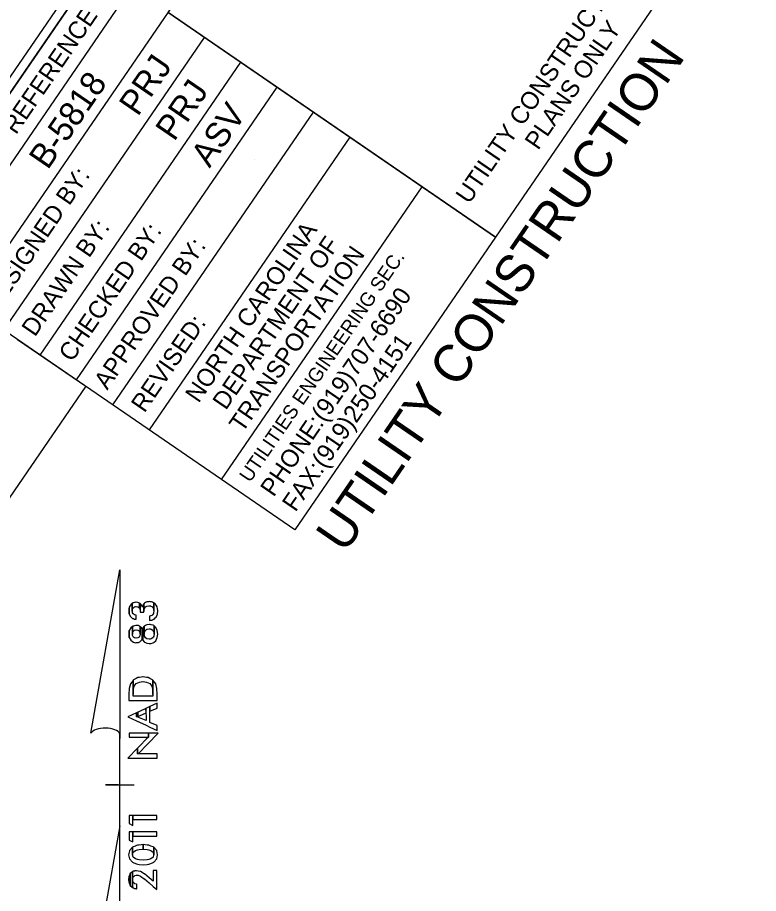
# Model space of a CAD drawing. Extents: x 1439200 to 1641919, y 393684 to 606444.
# Drawn here: x 1641528.9 to 1641613.1, y 394338.4 to 394437.9 of the extents above; entities that cross this region are included whole.
import ezdxf

# ---------------------------------------------------------------- set-up
doc = ezdxf.new("R2010")
doc.units = 0
for name, color, linetype in [('North Arrow NAD83 CELL', 7, 'Continuous'), ('Sheet Data Field CELL', 7, 'Continuous'), ('Sheet Plot Border Inside CELL', 7, 'Continuous'), ('Sheet Sticker Exception Certification CELL', 7, 'Continuous'), ('UC Plan Sheet 34 CELL', 7, 'Continuous')]:
    doc.layers.add(name, color=color, linetype=linetype)

msp = doc.modelspace()

# ---------------------------------------------------------------- linework, layer by layer
at = {"layer": 'North Arrow NAD83 CELL'}
for p, q in [((1641537.276, 394356.616), (1641540.564, 394375.155)), ((1641540.584, 394375.155), (1641540.564, 394375.155)), ((1641540.584, 394375.155), (1641540.564, 394375.155)), ((1641540.584, 394375.155), (1641540.576, 394356.035)), ((1641540.572, 394346.115), (1641540.576, 394356.595)), ((1641540.576, 394356.035), (1641540.576, 394356.575)), ((1641538.974, 394350.755), (1641538.954, 394350.755)), ((1641540.394, 394350.755), (1641538.974, 394350.755)), ((1641538.994, 394350.755), (1641542.194, 394350.754)), ((1641540.572, 394346.115), (1641537.224, 394327.216)), ((1641540.584, 394327.295), (1641540.572, 394346.115))]:
    msp.add_line(p, q, dxfattribs=at)
for points in [[(1641542.372, 394369.561), (1641542.411, 394369.557), (1641542.411, 394370.028), (1641542.372, 394370.03), (1641542.257, 394370.057), (1641542.241, 394370.061), (1641542.239, 394370.062), (1641542.103, 394370.158), (1641542.097, 394370.168), (1641542.086, 394370.186), (1641542.019, 394370.305), (1641542.005, 394370.388), (1641542.001, 394370.412), (1641541.985, 394370.502), (1641541.985, 394371.368), (1641541.812, 394371.25), (1641541.764, 394371.168), (1641541.764, 394371.167), (1641541.625, 394370.927), (1641541.612, 394370.834), (1641541.612, 394370.173), (1641541.626, 394370.147), (1641541.765, 394369.864), (1641541.812, 394369.824), (1641541.985, 394369.678), (1641542.001, 394369.665), (1641542.005, 394369.664), (1641542.02, 394369.658), (1641542.086, 394369.634), (1641542.097, 394369.63), (1641542.103, 394369.628), (1641542.239, 394369.579), (1641542.241, 394369.578), (1641542.258, 394369.572)], [(1641542.732, 394370.891), (1641542.788, 394370.85), (1641542.787, 394371.398), (1641542.732, 394371.433), (1641542.628, 394371.453), (1641542.43, 394371.49), (1641542.415, 394371.493), (1641542.41, 394371.492), (1641542.371, 394371.485), (1641542.257, 394371.466), (1641542.24, 394371.463), (1641542.238, 394371.463), (1641542.238, 394371.463), (1641542.102, 394371.44), (1641542.096, 394371.439), (1641542.086, 394371.437), (1641542.019, 394371.391), (1641542.004, 394371.381), (1641542, 394371.378), (1641541.985, 394371.368), (1641541.985, 394370.502), (1641542.001, 394370.653), (1641542.005, 394370.693), (1641542.019, 394370.72), (1641542.086, 394370.845), (1641542.096, 394370.864), (1641542.102, 394370.868), (1641542.238, 394370.966), (1641542.24, 394370.967), (1641542.257, 394370.971), (1641542.371, 394370.992), (1641542.41, 394370.999), (1641542.416, 394371.001), (1641542.43, 394371.004), (1641542.628, 394370.969)], [(1641542.788, 394370.85), (1641542.869, 394370.684), (1641542.869, 394371.347), (1641542.787, 394371.398)], [(1641543.183, 394370.345), (1641543.31, 394370.345), (1641543.31, 394371.316), (1641543.183, 394371.147), (1641543.123, 394370.942), (1641543.083, 394371.092), (1641542.964, 394371.287), (1641542.894, 394371.331), (1641542.893, 394371.332), (1641542.869, 394371.347), (1641542.869, 394370.684), (1641542.893, 394370.492), (1641542.894, 394370.344), (1641542.964, 394370.344), (1641543.084, 394370.344), (1641543.124, 394370.345)], [(1641544.407, 394370.708), (1641544.442, 394370.536), (1641544.442, 394371.396), (1641544.407, 394371.419), (1641544.393, 394371.429), (1641544.393, 394371.428), (1641544.282, 394371.501), (1641544.265, 394371.504), (1641544.259, 394371.505), (1641544.181, 394371.519), (1641544.077, 394371.539), (1641544.066, 394371.541), (1641543.946, 394371.563), (1641543.85, 394371.549), (1641543.648, 394371.522), (1641543.621, 394371.518), (1641543.479, 394371.443), (1641543.363, 394371.382), (1641543.357, 394371.379), (1641543.316, 394371.324), (1641543.31, 394371.316), (1641543.31, 394370.447), (1641543.316, 394370.599), (1641543.357, 394370.767), (1641543.364, 394370.792), (1641543.479, 394370.95), (1641543.621, 394371.034), (1641543.648, 394371.05), (1641543.85, 394371.086), (1641543.947, 394371.076), (1641544.066, 394371.064), (1641544.077, 394371.058), (1641544.182, 394371.005), (1641544.259, 394370.966), (1641544.265, 394370.957), (1641544.283, 394370.933), (1641544.393, 394370.78)], [(1641544.833, 394370.144), (1641544.867, 394370.547), (1641544.833, 394370.732), (1641544.788, 394370.973), (1641544.677, 394371.155), (1641544.589, 394371.3), (1641544.447, 394371.393), (1641544.442, 394371.396), (1641544.442, 394370.536), (1641544.408, 394370.243), (1641544.393, 394370.221), (1641544.283, 394370.06), (1641544.265, 394370.034), (1641544.259, 394370.03), (1641544.182, 394369.989), (1641544.078, 394369.935), (1641544.067, 394369.934), (1641543.947, 394369.926), (1641543.936, 394369.926), (1641543.936, 394369.429), (1641543.947, 394369.43), (1641544.067, 394369.447), (1641544.078, 394369.449), (1641544.182, 394369.464), (1641544.259, 394369.496), (1641544.266, 394369.499), (1641544.283, 394369.506), (1641544.393, 394369.552), (1641544.408, 394369.558), (1641544.443, 394369.573), (1641544.448, 394369.575), (1641544.59, 394369.721), (1641544.678, 394369.811), (1641544.789, 394370.049)], [(1641541.57, 394370.544), (1641541.612, 394370.174), (1641541.612, 394370.834)], [(1641544.415, 394368.126), (1641544.448, 394367.877), (1641544.447, 394368.805), (1641544.414, 394368.831), (1641544.36, 394368.875), (1641544.299, 394368.891), (1641544.118, 394368.939), (1641544.004, 394368.968), (1641544.001, 394368.969), (1641543.897, 394368.958), (1641543.897, 394368.957), (1641543.665, 394368.931), (1641543.64, 394368.928), (1641543.475, 394368.839), (1641543.474, 394368.839), (1641543.365, 394368.782), (1641543.353, 394368.775), (1641543.346, 394368.771), (1641543.338, 394368.762), (1641543.338, 394367.877), (1641543.346, 394367.943), (1641543.353, 394368.001), (1641543.366, 394368.1), (1641543.474, 394368.297), (1641543.475, 394368.298), (1641543.641, 394368.415), (1641543.665, 394368.434), (1641543.897, 394368.473), (1641544.001, 394368.454), (1641544.004, 394368.454), (1641544.118, 394368.434), (1641544.299, 394368.316), (1641544.36, 394368.216)], [(1641541.622, 394367.529), (1641541.627, 394367.493), (1641541.627, 394368.269), (1641541.621, 394368.26), (1641541.571, 394367.877), (1641541.571, 394367.877)], [(1641543.021, 394367.199), (1641543.104, 394367.352), (1641543.104, 394368.405), (1641543.02, 394368.569), (1641543.016, 394368.573), (1641542.891, 394368.712), (1641542.888, 394368.714), (1641542.86, 394368.73), (1641542.86, 394367.875), (1641542.833, 394367.677), (1641542.743, 394367.523), (1641542.676, 394367.479), (1641542.676, 394367.479), (1641542.673, 394367.477), (1641542.603, 394367.431), (1641542.431, 394367.399), (1641542.369, 394367.409), (1641542.249, 394367.43), (1641542.101, 394367.541), (1641542.099, 394367.544), (1641542.052, 394367.628), (1641542.015, 394367.695), (1641541.99, 394367.883), (1641541.99, 394368.73), (1641541.797, 394368.584), (1641541.627, 394368.269), (1641541.627, 394367.493), (1641541.798, 394367.169), (1641541.991, 394367.023), (1641542.015, 394367.005), (1641542.053, 394366.977), (1641542.099, 394366.965), (1641542.101, 394366.964), (1641542.249, 394366.926), (1641542.369, 394366.895), (1641542.431, 394366.902), (1641542.603, 394366.922), (1641542.673, 394366.931), (1641542.676, 394366.932), (1641542.743, 394366.966), (1641542.834, 394367.012), (1641542.86, 394367.025), (1641542.889, 394367.04), (1641542.891, 394367.041), (1641543.017, 394367.192)], [(1641542.833, 394368.081), (1641542.86, 394367.875), (1641542.86, 394368.73), (1641542.833, 394368.744), (1641542.742, 394368.793), (1641542.675, 394368.83), (1641542.672, 394368.83), (1641542.602, 394368.837), (1641542.43, 394368.854), (1641542.43, 394368.854), (1641542.368, 394368.861), (1641542.249, 394368.829), (1641542.1, 394368.789), (1641542.098, 394368.789), (1641542.052, 394368.777), (1641542.015, 394368.749), (1641541.99, 394368.73), (1641541.99, 394367.883), (1641542.015, 394368.061), (1641542.052, 394368.131), (1641542.098, 394368.221), (1641542.1, 394368.222), (1641542.249, 394368.327), (1641542.368, 394368.347), (1641542.43, 394368.359), (1641542.602, 394368.327), (1641542.672, 394368.28), (1641542.675, 394368.278), (1641542.742, 394368.233)], [(1641543.173, 394367.194), (1641543.179, 394367.183), (1641543.178, 394368.571), (1641543.173, 394368.565), (1641543.104, 394368.405), (1641543.104, 394367.352)], [(1641544.822, 394367.481), (1641544.868, 394367.879), (1641544.821, 394368.283), (1641544.82, 394368.285), (1641544.656, 394368.638), (1641544.654, 394368.639), (1641544.447, 394368.805), (1641544.448, 394367.877), (1641544.415, 394367.63), (1641544.36, 394367.539), (1641544.36, 394367.539), (1641544.299, 394367.439), (1641544.118, 394367.324), (1641544.005, 394367.302), (1641544.002, 394367.302), (1641543.898, 394367.283), (1641543.666, 394367.324), (1641543.641, 394367.341), (1641543.475, 394367.46), (1641543.474, 394367.461), (1641543.366, 394367.656), (1641543.354, 394367.754), (1641543.346, 394367.811), (1641543.338, 394367.877), (1641543.338, 394368.761), (1641543.178, 394368.571), (1641543.179, 394367.182), (1641543.338, 394366.992), (1641543.347, 394366.983), (1641543.354, 394366.974), (1641543.366, 394366.968), (1641543.474, 394366.913), (1641543.475, 394366.913), (1641543.641, 394366.829), (1641543.666, 394366.826), (1641543.898, 394366.799), (1641544.002, 394366.786), (1641544.005, 394366.786), (1641544.118, 394366.816), (1641544.3, 394366.865), (1641544.36, 394366.881), (1641544.415, 394366.925), (1641544.448, 394366.951), (1641544.655, 394367.118), (1641544.657, 394367.122), (1641544.821, 394367.473)], [(1641544.293, 394361.684), (1641544.311, 394361.618), (1641544.311, 394362.641), (1641544.292, 394362.665), (1641544.213, 394362.707), (1641543.97, 394362.838), (1641543.784, 394362.937), (1641543.61, 394362.961), (1641543.61, 394362.961), (1641543.198, 394363.018), (1641543.196, 394363.018), (1641542.781, 394362.96), (1641542.612, 394362.936), (1641542.421, 394362.834), (1641542.178, 394362.704), (1641542.104, 394362.664), (1641542.08, 394362.633), (1641542.068, 394362.617), (1641542.068, 394361.021), (1641542.081, 394361.617), (1641542.104, 394361.702), (1641542.178, 394361.968), (1641542.421, 394362.254), (1641542.612, 394362.348), (1641542.781, 394362.431), (1641543.196, 394362.482), (1641543.198, 394362.482), (1641543.61, 394362.431), (1641543.784, 394362.345), (1641543.97, 394362.255), (1641544.213, 394361.969)], [(1641544.776, 394360.319), (1641544.789, 394360.319), (1641544.788, 394361.017), (1641544.776, 394361.678), (1641544.636, 394362.221), (1641544.321, 394362.627), (1641544.322, 394360.834), (1641544.311, 394360.834), (1641544.293, 394360.834), (1641544.214, 394360.834), (1641543.97, 394360.834), (1641543.785, 394360.834), (1641543.611, 394360.834), (1641543.199, 394360.834), (1641543.197, 394360.834), (1641542.781, 394360.834), (1641542.613, 394360.834), (1641542.422, 394360.833), (1641542.179, 394360.833), (1641542.105, 394360.833), (1641542.081, 394360.833), (1641542.069, 394360.833), (1641542.068, 394362.617), (1641541.76, 394362.22), (1641541.621, 394361.677), (1641541.605, 394361.015), (1641541.605, 394360.318), (1641541.622, 394360.318), (1641541.761, 394360.318), (1641542.069, 394360.318), (1641542.081, 394360.318), (1641542.105, 394360.318), (1641542.179, 394360.318), (1641542.422, 394360.318), (1641542.613, 394360.318), (1641542.782, 394360.318), (1641543.197, 394360.319), (1641543.199, 394360.319), (1641543.611, 394360.319), (1641543.785, 394360.319), (1641543.971, 394360.319), (1641544.214, 394360.319), (1641544.293, 394360.319), (1641544.312, 394360.319), (1641544.322, 394360.319), (1641544.637, 394360.319)], [(1641544.311, 394361.618), (1641544.322, 394361.023), (1641544.321, 394362.627), (1641544.311, 394362.641)], [(1641543.969, 394359.111), (1641544.789, 394359.474), (1641544.789, 394360.021), (1641543.969, 394359.638)], [(1641543.97, 394357.321), (1641544.79, 394356.94), (1641544.79, 394357.484), (1641543.97, 394357.851), (1641543.969, 394359.638), (1641543.537, 394359.437), (1641543.538, 394358.044), (1641542.813, 394358.369), (1641542.811, 394358.37), (1641542.63, 394358.436), (1641542.625, 394358.437), (1641542.451, 394358.485), (1641542.451, 394358.93), (1641541.482, 394358.479), (1641542.451, 394358.028), (1641542.625, 394357.947), (1641542.63, 394357.945), (1641542.812, 394357.86), (1641542.814, 394357.859), (1641543.538, 394357.522)], [(1641542.451, 394358.485), (1641542.625, 394358.537), (1641542.625, 394359.011), (1641542.451, 394358.93)], [(1641542.813, 394358.607), (1641543.538, 394358.928), (1641543.537, 394359.437), (1641542.813, 394359.099), (1641542.811, 394359.098), (1641542.63, 394359.014), (1641542.625, 394359.011), (1641542.625, 394358.536), (1641542.63, 394358.539), (1641542.811, 394358.606)], [(1641543.607, 394356.165), (1641543.814, 394356.165), (1641543.814, 394356.64), (1641543.606, 394356.64), (1641543.429, 394356.64), (1641542.933, 394356.639), (1641542.742, 394356.639), (1641541.607, 394356.639), (1641541.607, 394356.164), (1641542.742, 394356.164), (1641542.933, 394356.164), (1641543.429, 394356.165)], [(1641544.791, 394356.512), (1641544.914, 394356.64), (1641544.791, 394356.64), (1641543.814, 394356.64), (1641543.814, 394356.165), (1641543.607, 394355.989), (1641543.43, 394355.816), (1641542.933, 394355.3), (1641542.743, 394355.103), (1641542.581, 394354.935), (1641542.581, 394354.27), (1641542.743, 394354.397), (1641542.934, 394354.578), (1641543.43, 394355.095), (1641543.607, 394355.279), (1641543.814, 394355.494)], [(1641543.815, 394353.797), (1641544.793, 394353.797), (1641544.792, 394354.271), (1641543.815, 394354.271), (1641543.607, 394354.271), (1641543.43, 394354.271), (1641542.934, 394354.271), (1641542.743, 394354.271), (1641542.581, 394354.27), (1641542.581, 394354.935), (1641541.484, 394353.796), (1641542.581, 394353.797), (1641542.743, 394353.797), (1641542.934, 394353.797), (1641543.43, 394353.797), (1641543.608, 394353.797)], [(1641541.622, 394346.353), (1641542.035, 394346.151), (1641542.035, 394347.281), (1641541.621, 394347.281)], [(1641542.035, 394346.807), (1641544.774, 394346.808), (1641544.774, 394347.282), (1641542.035, 394347.281)], [(1641541.623, 394344.477), (1641542.036, 394344.276), (1641542.035, 394345.406), (1641541.622, 394345.406)], [(1641542.036, 394344.932), (1641544.775, 394344.933), (1641544.775, 394345.407), (1641542.035, 394345.406)], [(1641544.766, 394342.372), (1641544.858, 394342.824), (1641544.766, 394343.265), (1641544.76, 394343.29), (1641544.416, 394343.665), (1641544.416, 394342.817), (1641544.41, 394342.795), (1641544.407, 394342.784), (1641544.34, 394342.547), (1641544.084, 394342.349), (1641544.082, 394342.348), (1641544.082, 394342.348), (1641543.853, 394342.285), (1641543.849, 394342.284), (1641543.684, 394342.239), (1641543.674, 394342.236), (1641543.215, 394342.196), (1641543.21, 394342.196), (1641543.205, 394342.196), (1641542.748, 394342.236), (1641542.573, 394342.283), (1641542.568, 394342.284), (1641542.346, 394342.344), (1641542.339, 394342.346), (1641542.08, 394342.546), (1641542.013, 394342.801), (1641542.011, 394342.809), (1641542.004, 394342.833), (1641542.004, 394343.672), (1641541.665, 394343.302), (1641541.661, 394343.283), (1641541.561, 394342.828), (1641541.561, 394342.827), (1641541.662, 394342.356), (1641541.666, 394342.351), (1641542.005, 394341.986), (1641542.011, 394341.979), (1641542.013, 394341.977), (1641542.08, 394341.949), (1641542.339, 394341.843), (1641542.346, 394341.84), (1641542.569, 394341.748), (1641542.574, 394341.747), (1641542.748, 394341.73), (1641543.205, 394341.681), (1641543.21, 394341.681), (1641543.216, 394341.681), (1641543.674, 394341.727), (1641543.684, 394341.728), (1641543.849, 394341.745), (1641543.853, 394341.746), (1641544.082, 394341.839), (1641544.084, 394341.84), (1641544.341, 394341.945), (1641544.408, 394341.972), (1641544.411, 394341.974), (1641544.417, 394341.981), (1641544.761, 394342.366)], [(1641542.747, 394343.416), (1641543.205, 394343.453), (1641543.204, 394343.968), (1641542.747, 394343.923), (1641542.573, 394343.906), (1641542.568, 394343.904), (1641542.568, 394343.903), (1641542.345, 394343.814), (1641542.345, 394343.814), (1641542.338, 394343.811), (1641542.079, 394343.707), (1641542.079, 394343.706), (1641542.012, 394343.68), (1641542.01, 394343.679), (1641542.004, 394343.672), (1641542.004, 394342.833), (1641542.011, 394342.855), (1641542.013, 394342.863), (1641542.08, 394343.104), (1641542.338, 394343.303), (1641542.345, 394343.308), (1641542.568, 394343.368), (1641542.573, 394343.369)], [(1641544.41, 394342.84), (1641544.416, 394342.817), (1641544.416, 394343.665), (1641544.41, 394343.671), (1641544.407, 394343.675), (1641544.34, 394343.702), (1641544.083, 394343.808), (1641544.081, 394343.809), (1641543.852, 394343.903), (1641543.848, 394343.905), (1641543.683, 394343.921), (1641543.673, 394343.922), (1641543.215, 394343.968), (1641543.209, 394343.968), (1641543.204, 394343.968), (1641543.205, 394343.452), (1641543.21, 394343.452), (1641543.215, 394343.452), (1641543.673, 394343.415), (1641543.684, 394343.415), (1641543.849, 394343.37), (1641543.853, 394343.369), (1641544.081, 394343.308), (1641544.083, 394343.306), (1641544.34, 394343.105), (1641544.407, 394342.852)], [(1641541.751, 394339.335), (1641541.757, 394339.325), (1641541.756, 394340.685), (1641541.751, 394340.681), (1641541.616, 394340.382), (1641541.6, 394340.346), (1641541.563, 394339.974), (1641541.563, 394339.973), (1641541.6, 394339.727), (1641541.616, 394339.617)], [(1641541.757, 394339.324), (1641541.992, 394339.103), (1641541.991, 394340.889), (1641541.756, 394340.685)], [(1641542.445, 394338.966), (1641542.502, 394338.961), (1641542.501, 394339.459), (1641542.445, 394339.464), (1641542.42, 394339.466), (1641542.414, 394339.468), (1641542.276, 394339.519), (1641542.262, 394339.529), (1641542.238, 394339.548), (1641542.122, 394339.637), (1641542.091, 394339.699), (1641542.033, 394339.817), (1641542.026, 394339.83), (1641542.017, 394340.076), (1641542.017, 394340.911), (1641541.991, 394340.889), (1641541.992, 394339.103), (1641542.017, 394339.092), (1641542.027, 394339.087), (1641542.033, 394339.085), (1641542.092, 394339.059), (1641542.122, 394339.045), (1641542.238, 394338.994), (1641542.263, 394338.983), (1641542.276, 394338.981), (1641542.414, 394338.969), (1641542.42, 394338.969)], [(1641544.365, 394339.229), (1641544.778, 394338.885), (1641544.777, 394341.016), (1641544.365, 394341.016), (1641544.365, 394339.805), (1641543.897, 394340.212), (1641543.352, 394340.657), (1641543.347, 394340.662), (1641542.921, 394340.914), (1641542.921, 394340.913), (1641542.91, 394340.92), (1641542.639, 394340.974), (1641542.501, 394341.001), (1641542.444, 394341.013), (1641542.419, 394341.007), (1641542.413, 394341.006), (1641542.275, 394340.977), (1641542.262, 394340.974), (1641542.237, 394340.968), (1641542.122, 394340.944), (1641542.122, 394340.944), (1641542.091, 394340.937), (1641542.032, 394340.925), (1641542.026, 394340.919), (1641542.017, 394340.912), (1641542.017, 394340.076), (1641542.026, 394340.102), (1641542.032, 394340.12), (1641542.091, 394340.289), (1641542.122, 394340.319), (1641542.237, 394340.433), (1641542.262, 394340.441), (1641542.275, 394340.446), (1641542.413, 394340.492), (1641542.42, 394340.492), (1641542.444, 394340.491), (1641542.501, 394340.49), (1641542.639, 394340.488), (1641542.91, 394340.381), (1641542.921, 394340.377), (1641543.347, 394340.077), (1641543.352, 394340.074), (1641543.897, 394339.619)]]:
    msp.add_lwpolyline(points, close=True, dxfattribs=at)
msp.add_ellipse((1641538.931, 394356.417), major_axis=(1.692, -0.013), ratio=0.461098, start_param=0.216388, end_param=2.908219, dxfattribs=at)
at = {"layer": 'Sheet Plot Border Inside CELL'}
msp.add_lwpolyline([(1641562.485, 394481.312), (1641185.491, 393931.556), (1641533.554, 393692.873), (1641910.548, 394242.628)], close=True, dxfattribs=at)
at = {"layer": 'Sheet Sticker Exception Certification CELL'}
for p, q in [((1641528.948, 394401.322), (1641536.701, 394396.006)), ((1641536.697, 394396.009), (1641491.444, 394330.019))]:
    msp.add_line(p, q, dxfattribs=at)
at = {"layer": 'UC Plan Sheet 34 CELL'}
for p, q in [((1641519.118, 394408.063), (1641564.325, 394473.987)), ((1641527.385, 394402.394), (1641550.174, 394435.626)), ((1641531.517, 394399.56), (1641554.306, 394432.792)), ((1641535.649, 394396.727), (1641558.438, 394429.959)), ((1641543.435, 394430.237), (1641543.435, 394430.237)), ((1641535.427, 394427.417), (1641535.427, 394427.417)), ((1641539.781, 394393.893), (1641562.57, 394427.125)), ((1641547.571, 394427.401), (1641547.571, 394427.401)), ((1641543.917, 394391.057), (1641566.706, 394424.289)), ((1641551.703, 394424.567), (1641551.703, 394424.567)), ((1641555.835, 394421.734), (1641555.835, 394421.734)), ((1641552.114, 394385.436), (1641574.903, 394418.668))]:
    msp.add_line(p, q, dxfattribs=at)
msp.add_lwpolyline([(1641560.499, 394476.611), (1641221.17, 393981.782), (1641567.551, 393744.252), (1641906.879, 394239.081)], close=True, dxfattribs=at)
for points in [[(1641515.291, 394410.687), (1641560.499, 394476.611), (1641568.44, 394471.165)], [(1641568.44, 394471.165), (1641523.233, 394405.241), (1641515.291, 394410.687)], [(1641605.656, 394445.645), (1641583.237, 394412.953), (1641546.038, 394438.462), (1641568.457, 394471.154)], [(1641546.022, 394438.473), (1641583.237, 394412.953), (1641560.448, 394379.721), (1641515.291, 394410.687)]]:
    msp.add_lwpolyline(points, dxfattribs=at)

# ---------------------------------------------------------------- texts
at = {"layer": 'Sheet Data Field CELL'}
for s, p in [('PRJ', (1641542.606, 394426.552)), ('B-5818', (1641532.379, 394420.496)), ('PRJ', (1641546.742, 394423.716)), ('ASV', (1641550.758, 394420.713))]:
    msp.add_text(s, height=2.8, rotation=55.55969, dxfattribs=at).set_placement(p)
at = {"layer": 'UC Plan Sheet 34 CELL'}
for s, height, p in [('UTILITY CONSTRUCTION', 2.00457, (1641580.225, 394416.606)), ('PROJECT REFERENCE NO.', 2.00457, (1641521.282, 394413.563)), ('PLANS ONLY', 2.0046, (1641588.068, 394422.729)), ('UTILITY CONSTRUCTION', 4.25, (1641566.111, 394376.925)), ('DESIGNED BY:', 2.00457, (1641526.479, 394404.264)), ('DRAWN BY:', 2.0046, (1641530.923, 394401.532)), ('CHECKED BY:', 2.00457, (1641535.132, 394398.67)), ('NORTH CAROLINA', 2.00457, (1641549.513, 394394.01)), ('DEPARTMENT OF', 2.00457, (1641552.605, 394393.205)), ('APPROVED BY:', 2.00457, (1641539.139, 394395.504)), ('TRANSPORTATION', 2.00457, (1641554.496, 394390.641)), ('UTILITIES ENGINEERING SEC.', 1.60366, (1641555.343, 394384.995)), ('PHONE:(919)707-6690', 2.00457, (1641558.034, 394383.349)), ('REVISED:', 2.0046, (1641543.36, 394392.906)), ('FAX:(919)250-4151', 2.00457, (1641560.512, 394381.649))]:
    msp.add_text(s, height=height, rotation=55.55969, dxfattribs=at).set_placement(p)

doc.saveas('drawing.dxf')
